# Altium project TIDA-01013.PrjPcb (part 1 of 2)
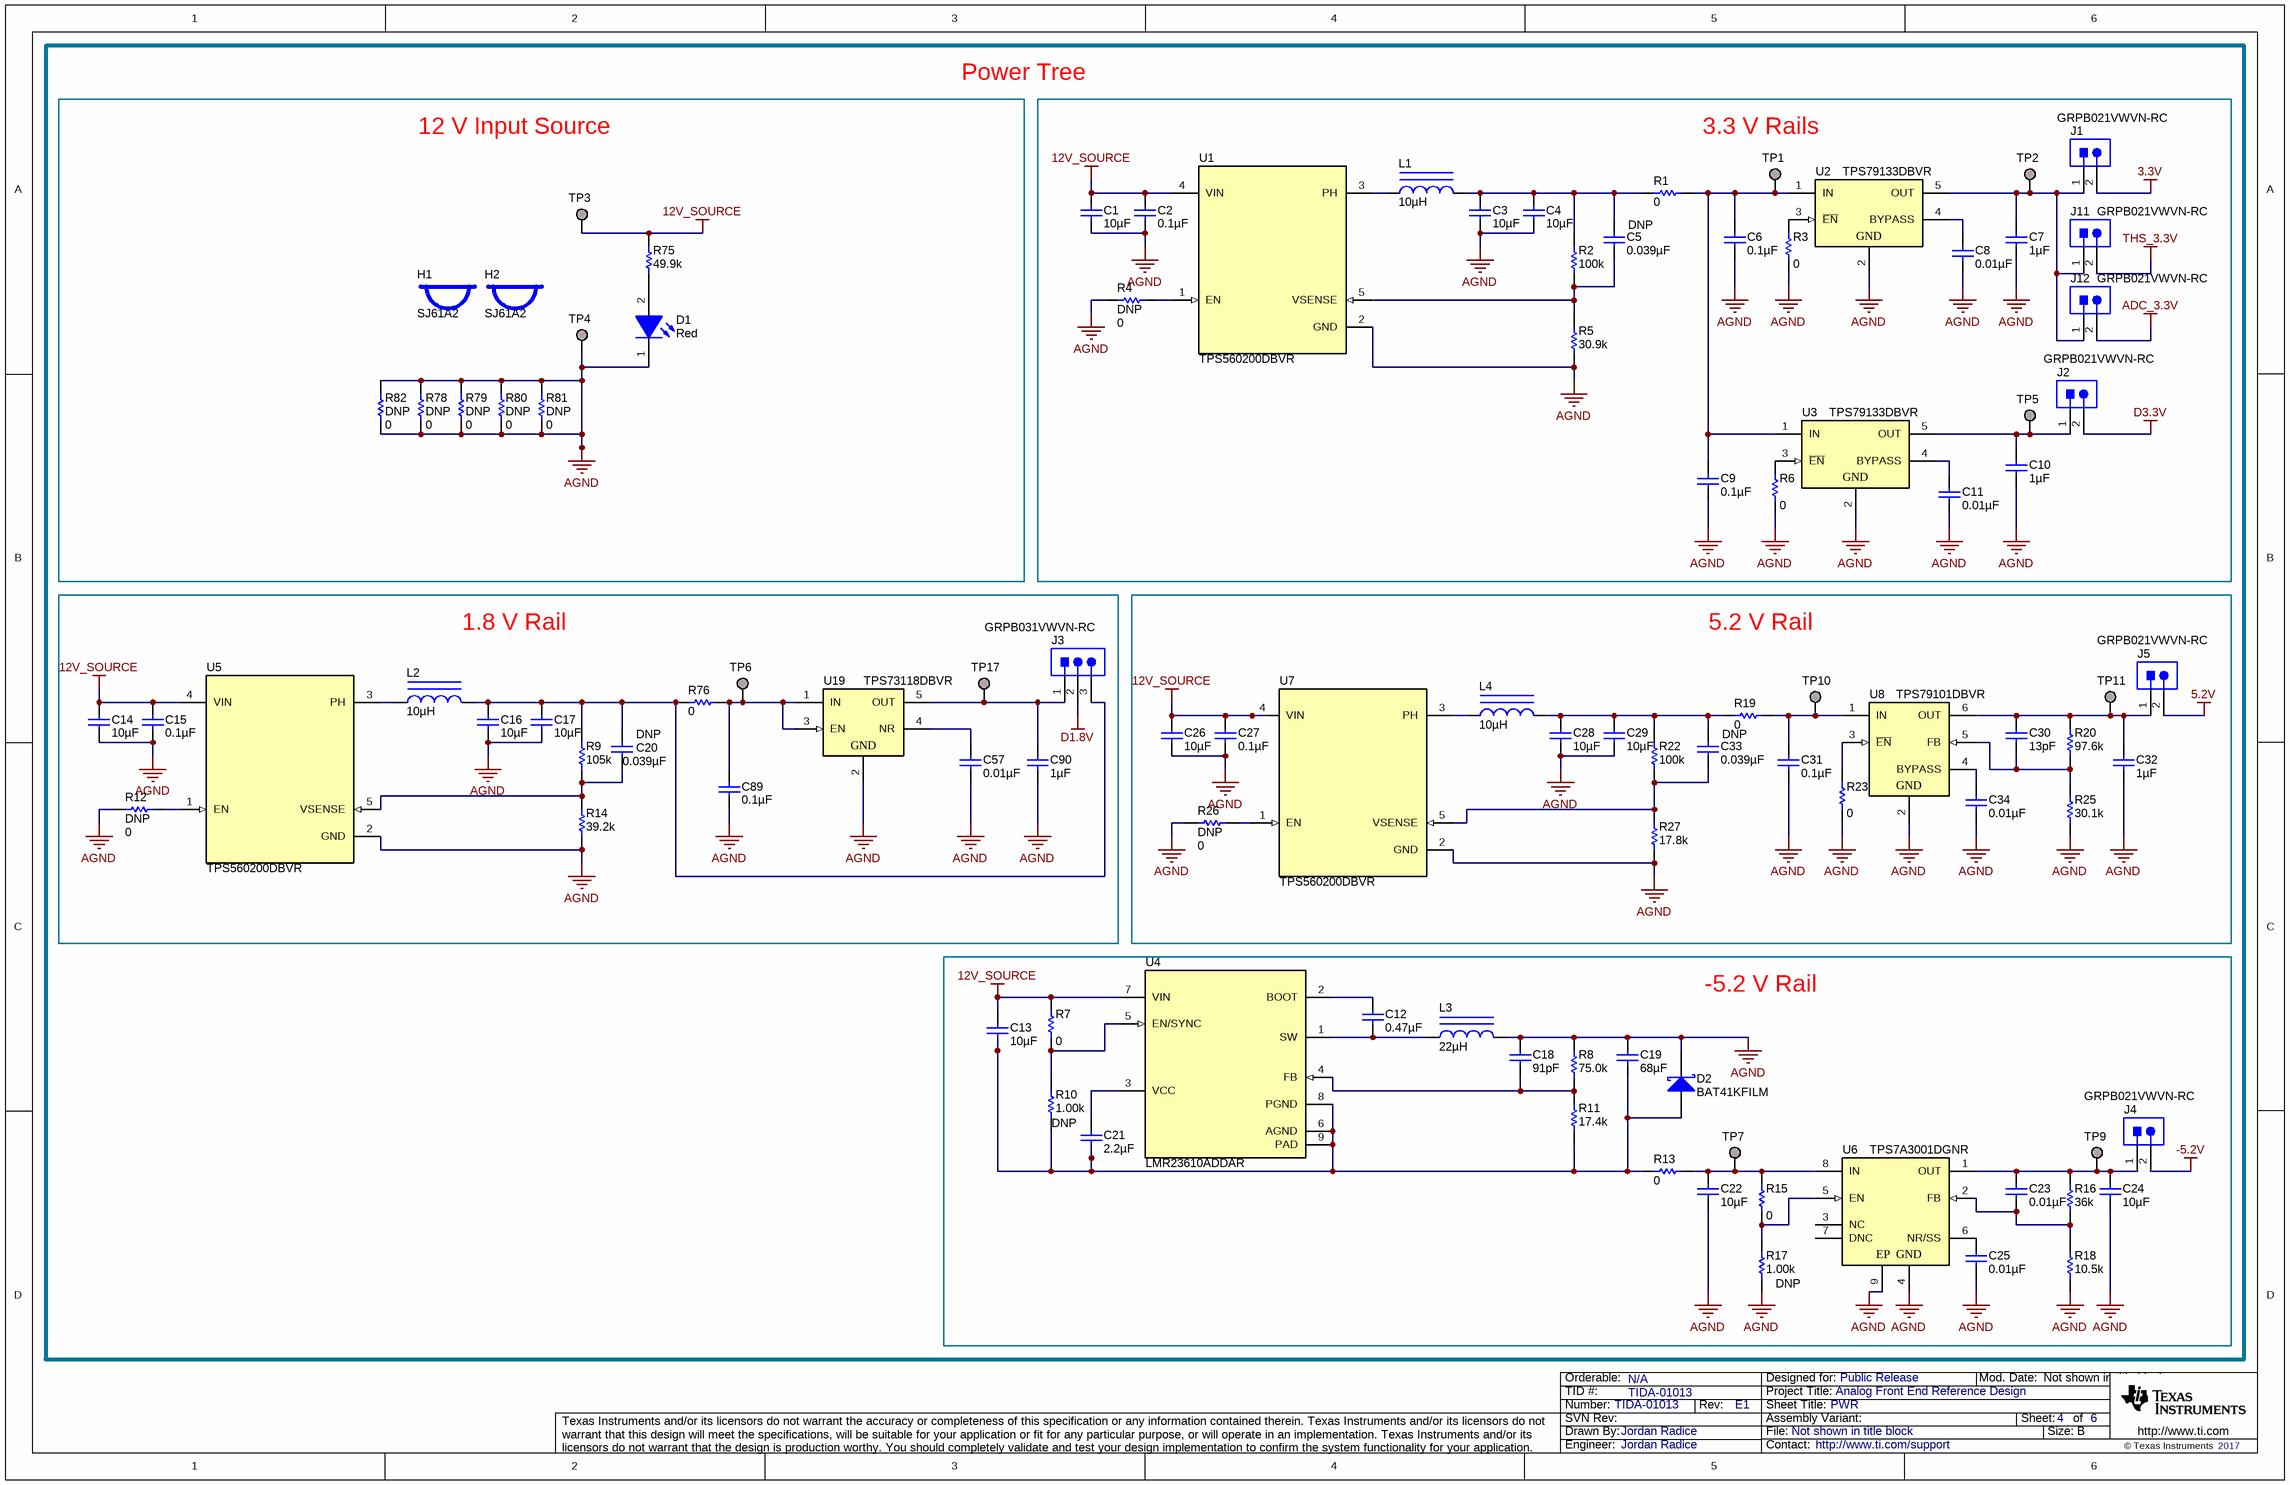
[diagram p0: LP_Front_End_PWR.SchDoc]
CopyrightYear: 2017; EVM_Orderable: N/A; PCB_Layout: Dee Lim; PCB_Rev: E1; PRJ_Customer: Public Release; PRJ_Engineer: Jordan Radice; PRJ_Number: TIDA-01013; PRJ_Title: Analog Front End Reference Design; SCH_Rev: E1; TechSupport: http://www.ti.com/support; TID: TIDA-01013
6 sheets, 219 parts. Net scope: global (net labels, ports and power ports of the same name join across sheets).
Board file: TIDA-01013.PcbDoc
Sheets:
  LP_Front_End_PWR.SchDoc
  LP_Front_End_ClockTree.SchDoc
  LP_Front_End_AFE.SchDoc
  LP_Front_End_ADC.SchDoc
  LP_Front_End_Block_Diagram.SchDoc
  TIDA-01013_EVM_Hardware.SchDoc

## Sheet LP_Front_End_PWR.SchDoc: PWR
size 431 x 279 mm; Date: Not shown in title block; ApprovedBy: Not shown in title block; CheckedBy: Not shown in title block; Author: Not shown in title block; CompanyName: Not shown in title block; DrawnBy: Jordan Radice; Engineer: Not shown in title block; Organization: Not shown in title block; Address1: Not shown in title block; Address2: Not shown in title block; Address3: Not shown in title block; Address4: Not shown in title block; DocumentNumber: 1; Revision: Use project parameter SCH_Rev; SheetNumber: 4; SheetTotal: 6; PageSetup: Record=PageOptions¦CenterHorizontal=True¦CenterVertical=True¦PrintScale=0.96¦XCorrection=1.00¦YCorrection=1.00¦PrintKind=0¦BorderSize=5000000¦LeftOffset=0¦BottomOffset=0¦Orientation=2¦PaperLength=1000¦PaperWidth=1000¦Scale=100¦PaperSource=15¦PrintQuality=-3¦MediaType=1¦DitherType=10¦PrintScaleMode=1¦PaperKind=11x17¦PaperIndex=17

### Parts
C1  ValueDisplayed: 10µF  [0603]  (hidden comment: C1608X5R1E106M080AC)
C2  ValueDisplayed: 0.1µF  [0402]  (hidden comment: GRM155R61E104KA87D)
C3  ValueDisplayed: 10µF  [0603]  (hidden comment: C1608X5R1E106M080AC)
C4  ValueDisplayed: 10µF  [0603]  (hidden comment: C1608X5R1E106M080AC)
C5  DNP  ValueDisplayed: 0.039µF  [0402]
C6  ValueDisplayed: 0.1µF  [0402]  (hidden comment: GRM155R61E104KA87D)
C7  ValueDisplayed: 1µF  [0402]  (hidden comment: GRM155R61E105KA12D)
C8  ValueDisplayed: 0.01µF  [0603]  (hidden comment: GRM188R61H103KA01D)
C9  ValueDisplayed: 0.1µF  [0402]  (hidden comment: GRM155R61E104KA87D)
C10  ValueDisplayed: 1µF  [0402]  (hidden comment: GRM155R61E105KA12D)
C11  ValueDisplayed: 0.01µF  [0603]  (hidden comment: GRM188R61H103KA01D)
C12  ValueDisplayed: 0.47µF  [0603]  (hidden comment: GRM188R61E474KA12D)
C13  ValueDisplayed: 10µF  [0603]  (hidden comment: C1608X5R1E106M080AC)
C14  ValueDisplayed: 10µF  [0603]  (hidden comment: C1608X5R1E106M080AC)
C15  ValueDisplayed: 0.1µF  [0402]  (hidden comment: GRM155R61E104KA87D)
C16  ValueDisplayed: 10µF  [0603]  (hidden comment: C1608X5R1E106M080AC)
C17  ValueDisplayed: 10µF  [0603]  (hidden comment: C1608X5R1E106M080AC)
C18  ValueDisplayed: 91pF  [0402]  (hidden comment: GRM1555C1H910JA01D)
C19  ValueDisplayed: 68µF  [1206_190]  (hidden comment: C3216X5R1A686M160AC)
C20  DNP  ValueDisplayed: 0.039µF  [0402]
C21  ValueDisplayed: 2.2µF  [0402]  (hidden comment: C1005X5R1E225K050BC)
C22  ValueDisplayed: 10µF  [0603]  (hidden comment: C1608X5R1E106M080AC)
C23  ValueDisplayed: 0.01µF  [0603]  (hidden comment: GRM188R61H103KA01D)
C24  ValueDisplayed: 10µF  [0603]  (hidden comment: C1608X5R1E106M080AC)
C25  ValueDisplayed: 0.01µF  [0603]  (hidden comment: GRM188R61H103KA01D)
C26  ValueDisplayed: 10µF  [0603]  (hidden comment: C1608X5R1E106M080AC)
C27  ValueDisplayed: 0.1µF  [0402]  (hidden comment: GRM155R61E104KA87D)
C28  ValueDisplayed: 10µF  [0603]  (hidden comment: C1608X5R1E106M080AC)
C29  ValueDisplayed: 10µF  [0603]  (hidden comment: C1608X5R1E106M080AC)
C30  ValueDisplayed: 13pF  [0402]  (hidden comment: GRM1555C1H130JA01D)
C31  ValueDisplayed: 0.1µF  [0402]  (hidden comment: GRM155R61E104KA87D)
C32  ValueDisplayed: 1µF  [0402]  (hidden comment: GRM155R61E105KA12D)
C33  DNP  ValueDisplayed: 0.039µF  [0402]
C34  ValueDisplayed: 0.01µF  [0603]  (hidden comment: GRM188R61H103KA01D)
C57  ValueDisplayed: 0.01µF  [0603]  (hidden comment: GRM188R61H103KA01D)
C89  ValueDisplayed: 0.1µF  [0402]  (hidden comment: GRM155R61E104KA87D)
C90  ValueDisplayed: 1µF  [0402]  (hidden comment: GRM155R61E105KA12D)
D1  value Red  [WL-SMCW_RED]  (hidden comment: 150060RS75000)
D2  BAT41KFILM  [SOD-523]
H1  SJ61A2  [Bumpon_SJ61A2]
H2  SJ61A2  [Bumpon_SJ61A2]
J1  GRPB021VWVN-RC  [Sullins_GRPB021VWVN-RC]
J2  GRPB021VWVN-RC  [Sullins_GRPB021VWVN-RC]
J3  GRPB031VWVN-RC  [Sullins_GRPB031VWVN-RC]
J4  GRPB021VWVN-RC  [Sullins_GRPB021VWVN-RC]
J5  GRPB021VWVN-RC  [Sullins_GRPB021VWVN-RC]
J11  GRPB021VWVN-RC  [Sullins_GRPB021VWVN-RC]
J12  GRPB021VWVN-RC  [Sullins_GRPB021VWVN-RC]
L1  ValueDisplayed: 10µH  [SRN2010TA]  (hidden comment: SRN2010TA-100M)
L2  ValueDisplayed: 10µH  [SRN2010TA]  (hidden comment: SRN2010TA-100M)
L3  ValueDisplayed: 22µH  [SRU2016]  (hidden comment: SRU2016-220Y)
L4  ValueDisplayed: 10µH  [SRN2010TA]  (hidden comment: SRN2010TA-100M)
R1  ValueDisplayed: 0  [0603]  (hidden comment: CRCW06030000Z0EA)
R2  ValueDisplayed: 100k  [0402]  (hidden comment: CRCW0402100KFKED)
R3  ValueDisplayed: 0  [0402]
R4  DNP  ValueDisplayed: 0  [0402]
R5  ValueDisplayed: 30.9k  [0402]  (hidden comment: CRCW040230K9FKED)
R6  ValueDisplayed: 0  [0402]
R7  ValueDisplayed: 0  [0402]
R8  ValueDisplayed: 75.0k  [0402]  (hidden comment: CRCW040275K0FKED)
R9  ValueDisplayed: 105k  [0402]  (hidden comment: CRCW0402105KFKED)
R10  DNP  ValueDisplayed: 1.00k  [0402]
R11  ValueDisplayed: 17.4k  [0402]  (hidden comment: CRCW040217K4FKED)
R12  DNP  ValueDisplayed: 0  [0402]
R13  ValueDisplayed: 0  [0603]  (hidden comment: CRCW06030000Z0EA)
R14  ValueDisplayed: 39.2k  [0402]  (hidden comment: CRCW040239K2FKED)
R15  ValueDisplayed: 0  [0402]
R16  ValueDisplayed: 36k  [0402]  (hidden comment: CRCW040236K0JNED)
R17  DNP  ValueDisplayed: 1.00k  [0402]
R18  ValueDisplayed: 10.5k  [0402]  (hidden comment: CRCW040210K5FKED)
R19  ValueDisplayed: 0  [0603]  (hidden comment: CRCW06030000Z0EA)
R20  ValueDisplayed: 97.6k  [0402]  (hidden comment: ERJ-2RKF9762X)
R22  ValueDisplayed: 100k  [0402]  (hidden comment: RC0402FR-07100KL)
R23  ValueDisplayed: 0  [0402]
R25  ValueDisplayed: 30.1k  [0402]  (hidden comment: RC0402FR-0730K1L)
R26  DNP  ValueDisplayed: 0  [0402]
R27  ValueDisplayed: 17.8k  [0402]  (hidden comment: CRCW040217K8FKED)
R75  ValueDisplayed: 49.9k  [0402]  (hidden comment: PCF0402-03-49K9BT1)
R76  ValueDisplayed: 0  [0603]  (hidden comment: CRCW06030000Z0EA)
R78  DNP  ValueDisplayed: 0  [0603]
R79  DNP  ValueDisplayed: 0  [0603]
R80  DNP  ValueDisplayed: 0  [0603]
R81  DNP  ValueDisplayed: 0  [0603]
R82  DNP  ValueDisplayed: 0  [0603]
TP1  TESTPOINT  [TP_SM_1MM]  (value not drawn)  (no BOM)
TP2  TESTPOINT  [TP_SM_1MM]  (value not drawn)  (no BOM)
TP3  TESTPOINT  [Keystone_5019]  (value not drawn)  (no BOM)
TP4  TESTPOINT  [Keystone_5019]  (value not drawn)  (no BOM)
TP5  TESTPOINT  [TP_SM_1MM]  (value not drawn)  (no BOM)
TP6  TESTPOINT  [TP_SM_1MM]  (value not drawn)  (no BOM)
TP7  TESTPOINT  [TP_SM_1MM]  (value not drawn)  (no BOM)
TP9  TESTPOINT  [TP_SM_1MM]  (value not drawn)  (no BOM)
TP10  TESTPOINT  [TP_SM_1MM]  (value not drawn)  (no BOM)
TP11  TESTPOINT  [TP_SM_1MM]  (value not drawn)  (no BOM)
TP17  TESTPOINT  [TP_SM_1MM]  (value not drawn)  (no BOM)
U1  TPS560200DBVR  [DBV0005A_N]
U2  TPS79133DBVR  [DBV0005A_N]
U3  TPS79133DBVR  [DBV0005A_N]
U4  LMR23610ADDAR  [DDA0008E_N]
U5  TPS560200DBVR  [DBV0005A_N]
U6  TPS7A3001DGNR  [DGN0008D_N]
U7  TPS560200DBVR  [DBV0005A_N]
U8  TPS79101DBVR  [DBV0006A_N]
U19  TPS73118DBVR  [DBV0005A_N]

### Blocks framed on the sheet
12 V Input Source: D1 H1 H2 R75 R78-R82 TP3 TP4
3.3 V Rails: C1-C11 J1 J2 J11 J12 L1 R1-R6 TP1 TP2 TP5 U1-U3
1.8 V Rail: C14-C17 C20 C57 C89 C90 J3 L2 R9 R12 R14 R76 TP6 TP17 U5 U19
5.2 V Rail: C26-C34 J5 L4 R19 R20 R22 R23 R25-R27 TP10 TP11 U7 U8
-5.2 V Rail: C12 C13 C18 C19 C21-C25 D2 J4 L3 R7 R8 R10 R11 R13 R15-R18 TP7 TP9 U4 U6

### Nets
3.3V: J1.2
5.2V: J5.2
12V_SOURCE: C1.1 C2.1 C13.1 C14.1 C15.1 C26.1 C27.1 R7.1 R75.2 TP3.1 U1.4(VIN) U4.7(VIN) U5.4(VIN) U7.4(VIN)
-5.2V: J4.2
ADC_3.3V: J12.2
AGND: C1.2 C2.2 C3.2 C4.2 C6.2 C7.2 C8.2 C9.2 C10.2 C11.2 C14.2 C15.2 C16.2 C17.2 C18.1 C19.1 C22.2 C24.2 C25.2 C26.2 C27.2 C28.2 C29.2 C31.2 C32.2 C34.2 C57.2 C89.2 C90.2 D1.1(K) D2.1(K) L3.2 R3.2 R4.2 R5.1 R6.2 R8.2 R12.2 R14.1 R17.1 R18.1 R23.2 R25.1 R26.2 R27.1 R78.1 R78.2 R79.1 R79.2 R80.1 R80.2 R81.1 R81.2 R82.1 R82.2 TP4.1 U1.2(GND) U2.2(GND) U3.2(GND) U5.2(GND) U6.4(GND) U6.9(EP) U7.2(GND) U8.2(GND) U19.2(GND)
D1.8V: J3.2
D3.3V: J2.2
THS_3.3V: J11.2
NetC3_1: C3.1 C4.1 C5.1 L1.2 R1.1 R2.2
NetC5_2: C5.2 R2.1 R5.2 U1.5(VSENSE)
NetC6_1: C6.1 C9.1 R1.2 TP1.1 U2.1(IN) U3.1(IN)
NetC7_1: C7.1 J1.1 J11.1 J12.1 TP2.1 U2.5(OUT)
NetC8_1: C8.1 U2.4(BYPASS)
NetC10_1: C10.1 J2.1 TP5.1 U3.5(OUT)
NetC11_1: C11.1 U3.4(BYPASS)
NetC12_1: C12.1 U4.2(BOOT)
NetC12_2: C12.2 L3.1 U4.1(SW)
NetC13_2: C13.2 C19.2 C21.2 D2.2(A) R10.1 R11.1 R13.1 U4.6(AGND) U4.8(PGND) U4.9(PAD)
NetC16_1: C16.1 C17.1 C20.1 J3.3 L2.2 R9.2 R76.1
NetC18_2: C18.2 R8.1 R11.2 U4.4(FB)
NetC20_2: C20.2 R9.1 R14.2 U5.5(VSENSE)
NetC21_1: C21.1 U4.3(VCC)
NetC22_1: C22.1 R13.2 R15.1 TP7.1 U6.8(IN)
NetC23_1: C23.1 C24.1 J4.1 R16.2 TP9.1 U6.1(OUT)
NetC23_2: C23.2 R16.1 R18.2 U6.2(FB)
NetC25_1: C25.1 U6.6(NR/SS)
NetC28_1: C28.1 C29.1 C33.1 L4.2 R19.1 R22.2
NetC30_1: C30.1 C32.1 J5.1 R20.2 TP11.1 U8.6(OUT)
NetC30_2: C30.2 R20.1 R25.2 U8.5(FB)
NetC31_1: C31.1 R19.2 TP10.1 U8.1(IN)
NetC33_2: C33.2 R22.1 R27.2 U7.5(VSENSE)
NetC34_1: C34.1 U8.4(BYPASS)
NetC57_1: C57.1 U19.4(NR)
NetC89_1: C89.1 R76.2 TP6.1 U19.1(IN) U19.3(EN)
NetC90_1: C90.1 J3.1 TP17.1 U19.5(OUT)
NetD1_2: D1.2(A) R75.1
NetL1_1: L1.1 U1.3(PH)
NetL2_1: L2.1 U5.3(PH)
NetL4_1: L4.1 U7.3(PH)
NetR3_1: R3.1 U2.3(~{EN})
NetR4_1: R4.1 U1.1(EN)
NetR6_1: R6.1 U3.3(~{EN})
NetR7_2: R7.2 R10.2 U4.5(EN/SYNC)
NetR12_1: R12.1 U5.1(EN)
NetR15_2: R15.2 R17.2 U6.5(EN)
NetR23_1: R23.1 U8.3(~{EN})
NetR26_1: R26.1 U7.1(EN)

Not connected (* = marked no-connect by the designer): U6 3(NC) 7(DNC)

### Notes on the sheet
- Power Tree

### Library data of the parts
C1 C3 C4 C13 C14 C16 C17 C22 C24 C26 C28 C29 = C1608X5R1E106M080AC: CAP, CERM, 10 µF, 25 V, +/- 20%, X5R, 0603; Manufacturer: TDK; Polarized: N; CompType: Capacitor; Value: 10uF; U/M: EA; Cap_F: 0.00001; Tolerance_%: 20; ESR_ohm: 0.004639; Value1: 0.004639 ohm; VDC_V: 25; Value2: 25V; IRMS_A: 2.41407; TaMin_C: -55; TaMax_C: 85; SizeArea_mm2: 1.28; SizeAreaWB_mm2: 4.68; SizeX_mm: 1.6; SizeY_mm: 0.8; SizeZ_mm: 1; AEC Category: Q200
C2 C6 C9 C15 C27 C31 C89 = GRM155R61E104KA87D: CAP, CERM, 0.1 µF, 25 V, +/- 10%, X5R, 0402; Manufacturer: MuRata; Polarized: N; CompType: Capacitor; Value: 0.1uF; U/M: EA; Cap_F: 0.0000001; Tolerance_%: 10; Value1: Unknown; VDC_V: 25; Value2: 25V; TaMin_C: -55; TaMax_C: 85; SizeArea_mm2: 0.5; SizeAreaWB_mm2: 3; SizeX_mm: 1; SizeZ_mm: 0.6; AEC Category: Q200
C5 C20 C33 = GRM155R71A393KA01D: CAP, CERM, 0.039 µF, 10 V, +/- 10%, X7R, 0402; Manufacturer: MuRata; Polarized: N; CompType: Capacitor; Value: 0.039uF; U/M: EA; Cap_F: 0.000000039; Tolerance_%: 10; Value1: Unknown; Value2: 10V; TaMin_C: -55; TaMax_C: 125; SizeArea_mm2: 0.5; SizeAreaWB_mm2: 3; SizeX_mm: 1; SizeZ_mm: 0.6; AEC Category: Q200
C7 C10 C32 C90 = GRM155R61E105KA12D: CAP, CERM, 1 µF, 25 V, +/- 10%, X5R, 0402; Manufacturer: MuRata; Polarized: N; CompType: Capacitor; Value: 1uF; U/M: EA; Cap_F: 0.000001; Tolerance_%: 10; Value1: Unknown; VDC_V: 25; Value2: 25V; TaMin_C: -55; TaMax_C: 85; SizeArea_mm2: 0.5; SizeAreaWB_mm2: 3; SizeX_mm: 1; SizeZ_mm: 0.6; AEC Category: Q200
C8 C11 C23 C25 C34 C57 = GRM188R61H103KA01D: CAP, CERM, 0.01 µF, 50 V, +/- 10%, X5R, 0603; Manufacturer: MuRata; Polarized: N; CompType: Capacitor; Value: 0.01uF; U/M: EA; Cap_F: 0.00000001; Tolerance_%: 10; Value1: Unknown; VDC_V: 50; Value2: 50V; TaMin_C: -55; TaMax_C: 85; SizeArea_mm2: 1.28; SizeAreaWB_mm2: 4.68; SizeX_mm: 1.6; SizeY_mm: 0.8; SizeZ_mm: 1; AEC Category: Q200
C12 = GRM188R61E474KA12D: CAP, CERM, 0.47 µF, 25 V, +/- 10%, X5R, 0603; Manufacturer: MuRata; Polarized: N; CompType: Capacitor; Value: 0.47uF; U/M: EA; Cap_F: 0.00000047; Tolerance_%: 10; Value1: Unknown; VDC_V: 25; Value2: 25V; TaMin_C: -55; TaMax_C: 85; SizeArea_mm2: 1.28; SizeAreaWB_mm2: 4.68; SizeX_mm: 1.6; SizeY_mm: 0.8; SizeZ_mm: 1; AEC Category: Q200
C18 = GRM1555C1H910JA01D: CAP, CERM, 91 pF, 50 V, +/- 5%, C0G/NP0, 0402; Manufacturer: MuRata; Polarized: N; CompType: Capacitor; Value: 91pF; U/M: EA; Cap_F: 0.000000000091; Tolerance_%: 5; Value1: Unknown; VDC_V: 50; Value2: 50V; TaMin_C: -55; TaMax_C: 125; SizeArea_mm2: 0.5; SizeAreaWB_mm2: 3; SizeX_mm: 1; SizeZ_mm: 0.6; AEC Category: Q200
C19 = C3216X5R1A686M160AC: CAP, CERM, 68 µF, 10 V, +/- 20%, X5R, 1206_190; Manufacturer: TDK; Polarized: N; CompType: Capacitor; Value: 68uF; U/M: EA; Cap_F: 0.000068; Tolerance_%: 20; ESR_ohm: 0.003494; Value1: 0.003494 ohm; VDC_V: 10; Value2: 10V; IRMS_A: 3.8813; TaMin_C: -55; TaMax_C: 85; SizeArea_mm2: 5.12; SizeAreaWB_mm2: 10.92; SizeX_mm: 3.2; SizeY_mm: 1.6; SizeZ_mm: 1.9; AEC Category: Q200
C21 = C1005X5R1E225K050BC: CAP, CERM, 2.2 µF, 25 V, +/- 10%, X5R, 0402; Manufacturer: TDK; Polarized: N; CompType: Capacitor; Value: 2.2uF; U/M: EA; Cap_F: 0.0000022; Tolerance_%: 10; Value1: Unknown; VDC_V: 25; Value2: 25V; TaMin_C: -55; TaMax_C: 85; SizeArea_mm2: 0.5; SizeAreaWB_mm2: 3; SizeX_mm: 1; SizeZ_mm: 0.6; AEC Category: Q200
C30 = GRM1555C1H130JA01D: CAP, CERM, 13 pF, 50 V, +/- 5%, C0G/NP0, 0402; Manufacturer: MuRata; Polarized: N; CompType: Capacitor; Value: 13pF; U/M: EA; Cap_F: 0.000000000013; Tolerance_%: 5; Value1: Unknown; VDC_V: 50; Value2: 50V; TaMin_C: -55; TaMax_C: 125; SizeArea_mm2: 0.5; SizeAreaWB_mm2: 3; SizeX_mm: 1; SizeZ_mm: 0.6; AEC Category: Q200
D1 = 150060RS75000: LED, Red, SMD; Manufacturer: Wurth Elektronik; Type: AlInGaP; Vf_V: 2; Value2: 2V; Io_A: 0.03; Vr_V: 5; Tjmax_C: 85; Power_TotalModule: 0.072; Value1: 0.072W; Angle: 140; U/M: EA
D2 = BAT41KFILM: Diode, Schottky, 100 V, 0.2 A, SOD-523; Manufacturer: STMicroelectronics; U/M: EA; Vf_V: 1; Value: 100V; Value1: 0.2A; Value2: 1V; Io_A: 0.2; Vr_V: 100; TJmax_C: 150; SizeAreaWB_mm2: 5.13; SizeArea_mm2: 1.53; SizeX_mm: 1.7; SizeY_mm: 0.9; SizeZ_mm: 0.65; AEC Category: Q101; AEC Qualified: N
H1 H2 = SJ61A2: Bumpon, Hemisphere, 0.375 X 0.235, Black; Manufacturer: 3M; SymbolCreator: a0412235
J1 J2 J4 J5 J11 J12 = GRPB021VWVN-RC: Header, 50mil, 2x1, Gold, TH; Manufacturer: Sullins Connector Solutions; SymbolCreator: a0412235
J3 = GRPB031VWVN-RC: Header, 50mil, 3x1, Gold, TH; Manufacturer: Sullins Connector Solutions; SymbolCreator: a0799628; Gender: Male; Shrouded: N; Row_Count: 1
L1 L2 L4 = SRN2010TA-100M: Inductor, Shielded, Ferrite, 10 µH, 0.45 A, 0.864 ohm, AEC-Q200 Grade 1, SMD; Manufacturer: Bourns; Value: 10uH; Ind_H: 10.0E-6; Imax_A: 0.45; Irms: 0.45A @ 40C rise; Isat: 0.55A @ 30% inductance drop; DCR_ohm: 0.864; Value2: 0.45A; SizeAreaWB_mm2: 7.8; SizeArea_mm2: 3.2; SizeX_mm: 2; SizeY_mm: 1.6; SizeZ_mm: 1; AEC Category: Q200; AEC Qualified: Y
L3 = SRU2016-220Y: Inductor, Drum Core, Ferrite, 22 µH, 0.37 A, 0.99 ohm, SMD; Manufacturer: Bourns; Value: 22uH; Ind_H: 22.0E-6; Imax_A: 0.37; Irms: 0.43A @ 40C rise; Isat: 0.37A @ 35% inductance drop; DCR_ohm: 0.99; Value2: 0.37A; SizeAreaWB_mm2: 14.44; SizeArea_mm2: 7.84; SizeX_mm: 2.8; SizeZ_mm: 1.65; AEC Category: Q200
R1 R13 R19 R76 R78-R82 = CRCW06030000Z0EA: RES, 0, 5%, 0.1 W, 0603; Manufacturer: Vishay-Dale; CompType: Resistor; Value: 0; Value_Code: 0000; Tolerance_%: 5; Power_W: 0.1; Value2: 0.1W; VDC_V: 75; TempCo: 200 ppm/C; SizeArea_mm2: 1.28; SizeX_mm: 1.6; SizeY_mm: 0.8; SizeZ_mm: 1; EIA_Code: E24; U/M: EA; AEC Category: Q200
R2 = CRCW0402100KFKED: RES, 100 k, 1%, 0.063 W, 0402; Manufacturer: Vishay-Dale; CompType: Resistor; Value: 100k; Res_ohm: 100000; Tolerance_%: 1; Power_W: 0.063; Value2: 0.063W; VDC_V: 50; TempCo: 100 ppm/C; SizeArea_mm2: 0.5; SizeZ_mm: 0.6; EIA_Code: E96; U/M: EA; AEC Category: Q200
R3 R4 R6 R7 R12 R15 R23 R26 = CRCW04020000Z0ED: RES, 0, 5%, 0.063 W, 0402; Manufacturer: Vishay-Dale; CompType: Resistor; Value: 0; Value_Code: 0000; Tolerance_%: 5; Power_W: 0.063; Value2: 0.063W; VDC_V: 50; TempCo: 200 ppm/C; SizeArea_mm2: 0.5; SizeX_mm: 1; SizeZ_mm: 0.6; EIA_Code: E24; U/M: EA; AEC Category: Q200
R5 = CRCW040230K9FKED: RES, 30.9 k, 1%, 0.063 W, 0402; Manufacturer: Vishay-Dale; CompType: Resistor; Value: 30.9k; Res_ohm: 30900; Value_Code: 30k9; Tolerance_%: 1; Power_W: 0.063; Value2: 0.063W; VDC_V: 50; TempCo: 100 ppm/C; SizeArea_mm2: 0.5; SizeZ_mm: 0.6; EIA_Code: E96; U/M: EA; AEC Category: Q200
R8 = CRCW040275K0FKED: RES, 75.0 k, 1%, 0.063 W, 0402; Manufacturer: Vishay-Dale; CompType: Resistor; Value: 75.0k; Res_ohm: 75000; Value_Code: 75k0; Tolerance_%: 1; Power_W: 0.063; Value2: 0.063W; VDC_V: 50; TempCo: 100 ppm/C; SizeArea_mm2: 0.5; SizeZ_mm: 0.6; EIA_Code: E96; U/M: EA; AEC Category: Q200
R9 = CRCW0402105KFKED: RES, 105 k, 1%, 0.063 W, 0402; Manufacturer: Vishay-Dale; CompType: Resistor; Value: 105k; Res_ohm: 105000; Tolerance_%: 1; Power_W: 0.063; Value2: 0.063W; VDC_V: 50; TempCo: 100 ppm/C; SizeArea_mm2: 0.5; SizeZ_mm: 0.6; EIA_Code: E96; U/M: EA; AEC Category: Q200
R10 R17 = RC0402FR-071KL: RES, 1.00 k, 1%, 0.0625 W, 0402; Manufacturer: Yageo America; CompType: Resistor; Value: 1.00k; Res_ohm: 1000; Value_Code: 1k00; Tolerance_%: 1; Power_W: 0.0625; VDC_V: 50; TempCo: 100 ppm/C; SizeArea_mm2: 0.5; SizeZ_mm: 0.6; EIA_Code: E96; U/M: EA; AEC Category: Q200; AEC Qualified: N
R11 = CRCW040217K4FKED: RES, 17.4 k, 1%, 0.063 W, 0402; Manufacturer: Vishay-Dale; CompType: Resistor; Value: 17.4k; Res_ohm: 17400; Value_Code: 17k4; Tolerance_%: 1; Power_W: 0.063; Value2: 0.063W; VDC_V: 50; TempCo: 100 ppm/C; SizeArea_mm2: 0.5; SizeZ_mm: 0.6; EIA_Code: E96; U/M: EA; AEC Category: Q200
R14 = CRCW040239K2FKED: RES, 39.2 k, 1%, 0.063 W, 0402; Manufacturer: Vishay-Dale; CompType: Resistor; Value: 39.2k; Res_ohm: 39200; Value_Code: 39k2; Tolerance_%: 1; Power_W: 0.063; Value2: 0.063W; VDC_V: 50; TempCo: 100 ppm/C; SizeArea_mm2: 0.5; SizeZ_mm: 0.6; EIA_Code: E96; U/M: EA; AEC Category: Q200
R16 = CRCW040236K0JNED: RES, 36 k, 5%, 0.063 W, 0402; Manufacturer: Vishay-Dale; CompType: Resistor; Value: 36k; Res_ohm: 36000; Value_Code: 36k0; Tolerance_%: 5; Power_W: 0.063; Value2: 0.063W; VDC_V: 50; TempCo: 200 ppm/C; SizeArea_mm2: 0.5; SizeX_mm: 1; SizeZ_mm: 0.6; EIA_Code: E24; U/M: EA; AEC Category: Q200
R18 = CRCW040210K5FKED: RES, 10.5 k, 1%, 0.063 W, 0402; Manufacturer: Vishay-Dale; CompType: Resistor; Value: 10.5k; Res_ohm: 10500; Value_Code: 10k5; Tolerance_%: 1; Power_W: 0.063; Value2: 0.063W; VDC_V: 50; TempCo: 100 ppm/C; SizeArea_mm2: 0.5; SizeZ_mm: 0.6; EIA_Code: E96; U/M: EA; AEC Category: Q200
R20 = ERJ-2RKF9762X: RES, 97.6 k, 1%, 0.1 W, AEC-Q200 Grade 0, 0402; Manufacturer: Panasonic; CompType: Resistor; Value: 97.6k; Res_ohm: 97600; Value_Code: 97k6; Tolerance_%: 1; Power_W: 0.1; Value2: 0.1W; VDC_V: 50; TempCo: 100 ppm/C; SizeArea_mm2: 0.5; SizeZ_mm: 0.6; EIA_Code: E96; U/M: EA; AEC Category: Q200; AEC Qualified: Y; AEC Grade: 0
R22 = RC0402FR-07100KL: RES, 100 k, 1%, 0.0625 W, 0402; Manufacturer: Yageo America; CompType: Resistor; Value: 100k; Res_ohm: 100000; Tolerance_%: 1; Power_W: 0.0625; VDC_V: 50; TempCo: 100 ppm/C; SizeArea_mm2: 0.5; SizeZ_mm: 0.6; EIA_Code: E96; U/M: EA; AEC Category: Q200; AEC Qualified: N
R25 = RC0402FR-0730K1L: RES, 30.1 k, 1%, 0.063 W, 0402; Manufacturer: Yageo America; CompType: Resistor; Value: 30.1k; Res_ohm: 30100; Value_Code: 30k1; Tolerance_%: 1; Power_W: 0.063; Value2: 0.063W; VDC_V: 50; TempCo: 100 ppm/C; SizeArea_mm2: 0.5; SizeZ_mm: 0.6; EIA_Code: E96; U/M: EA; AEC Category: Q200; AEC Qualified: N
R27 = CRCW040217K8FKED: RES, 17.8 k, 1%, 0.063 W, 0402; Manufacturer: Vishay-Dale; CompType: Resistor; Value: 17.8k; Res_ohm: 17800; Value_Code: 17k8; Tolerance_%: 1; Power_W: 0.063; Value2: 0.063W; VDC_V: 50; TempCo: 100 ppm/C; SizeArea_mm2: 0.5; SizeZ_mm: 0.6; EIA_Code: E96; U/M: EA; AEC Category: Q200
R75 = PCF0402-03-49K9BT1: RES, 49.9 k, 0.1%, 0.063 W, 0402; Manufacturer: TT Electronics/IRC; CompType: Resistor; Value: 49.9k; Res_ohm: 49900; Value_Code: 49k9; Tolerance_%: 0.1; Power_W: 0.063; Value2: 0.063W; VDC_V: 25; TempCo: 25 ppm/C; SizeArea_mm2: 0.5; SizeX_mm: 1; SizeZ_mm: 0.6; EIA_Code: E192; U/M: EA; AEC Category: Q200; AEC Qualified: N
TP1 TP2 TP5-TP7 TP9-TP11 TP17 = TP_SM_1MM: 1mm Test Point, SMT; Manufacturer: Any
TP3 TP4 = 5019: Test Point, Miniature, SMT; Manufacturer: Keystone; CompType: Test Point Loop
U1 U5 U7 = TPS560200DBVR: 17V Input, 500mA Synchronous Step-Down Regulator in SOT-23 with Advanced Eco-Mode(TM), DBV0005A (SOT-5); Alternate PartNumber: TPS560200DBVT; Manufacturer: Texas Instruments; SymbolCreator: a0411947; SizeArea_mm2: 8.12; SizeAreaWB_mm2: 14.82; SizeX_mm: 2.8; SizeY_mm: 2.9; SizeZ_mm: 1.45; CompType: IC; U/M: EA
U2 U3 = TPS79133DBVR: Single Output High PSRR LDO, 100 mA, Fixed 3.3 V Output, 2.7 to 5.5 V Input, 5-pin SOT-23 (DBV), -40 to 125 degC, Green (RoHS & no Sb/Br); Manufacturer: Texas Instruments; Alternate PartNumber: Equivalent; Accuracy(%): 2; Fixed Output Options(V): 3.3; Iout(Max)(A): 0.1; Iq(Typ)(mA): 0.2; Rating: Catalog; SubFamily: Single Channel LDO; Vdo(Typ)(mV): 50; Vin(Max)(V): 5.5; Vin(Min)(V): 2.7
U4 = LMR23610ADDAR: SIMPLE SWITCHER, 36V 1A Synchronous Step-Down Converter, DDA0008E (SOIC-8); Manufacturer: Texas Instruments; SymbolCreator: a0411947; SizeArea_mm2: 31; SizeAreaWB_mm2: 57.4; SizeX_mm: 5; SizeY_mm: 6.2; SizeZ_mm: 1.7; CompType: IC; U/M: EA
U6 = TPS7A3001DGNR: Single Output High PSRR LDO, 200 mA, Adjustable -1.18 to -33 V Output, -3 to -36 V Input, with Ultra-Low Noise, 8-pin MSOP (DGN), -40 to 125 degC, Green (RoHS & no Sb/Br); Manufacturer: Texas Instruments; Alternate PartNumber: Equivalent; Accuracy(%): 1.5; Iout(Max)(A): 0.2; Iq(Typ)(mA): 0.05; SubFamily: Single Channel LDO; Vdo(Typ)(mV): 216
U8 = TPS79101DBVR: Single Output High PSRR LDO, 100 mA, Adjustable 1.2 to 5.5 V Output, 2.7 to 5.5 V Input, 6-pin SOT-23 (DBV), -40 to 125 degC, Green (RoHS & no Sb/Br); Manufacturer: Texas Instruments; Alternate PartNumber: Equivalent; Accuracy(%): 2; Iout(Max)(A): 0.1; Iq(Typ)(mA): 0.2; SubFamily: Single Channel LDO; Vdo(Typ)(mV): 38; Vin(Max)(V): 5.5; Vin(Min)(V): 2.7; Vout Adj(Min)(V): 1.2
U19 = TPS73118DBVR: Single Output Fast Transient Response LDO, 150 mA, Fixed 1.8 V Output, 1.7 to 5.5 V Input, 5-pin SOT-23 (DBV), -40 to 85 degC, Green (RoHS & no Sb/Br); Manufacturer: Texas Instruments; Alternate PartNumber: Equivalent; Accuracy(%): 1; Fixed Output Options(V): 1.8; Iout(Max)(A): 0.15; Iq(Typ)(mA): 0.4; SubFamily: Single Channel LDO; Vdo(Typ)(mV): 30; Vin(Max)(V): 5.5; Vin(Min)(V): 1.7

## Sheet LP_Front_End_ClockTree.SchDoc
size 431 x 279 mm; Date: Not shown in title block; ApprovedBy: Not shown in title block; CheckedBy: Not shown in title block; Author: Not shown in title block; CompanyName: Not shown in title block; Engineer: Not shown in title block; Organization: Not shown in title block; Address1: Not shown in title block; Address2: Not shown in title block; Address3: Not shown in title block; Address4: Not shown in title block; DocumentNumber: 1; Revision: Use project parameter SCH_Rev; SheetNumber: 5; SheetTotal: 6; PageSetup: Record=PageOptions¦CenterHorizontal=True¦CenterVertical=True¦PrintScale=0.96¦XCorrection=1.00¦YCorrection=1.00¦PrintKind=0¦BorderSize=5000000¦LeftOffset=0¦BottomOffset=0¦Orientation=2¦PaperLength=1000¦PaperWidth=1000¦Scale=100¦PaperSource=15¦PrintQuality=-3¦MediaType=1¦DitherType=10¦PrintScaleMode=1¦PaperKind=11x17¦PaperIndex=17
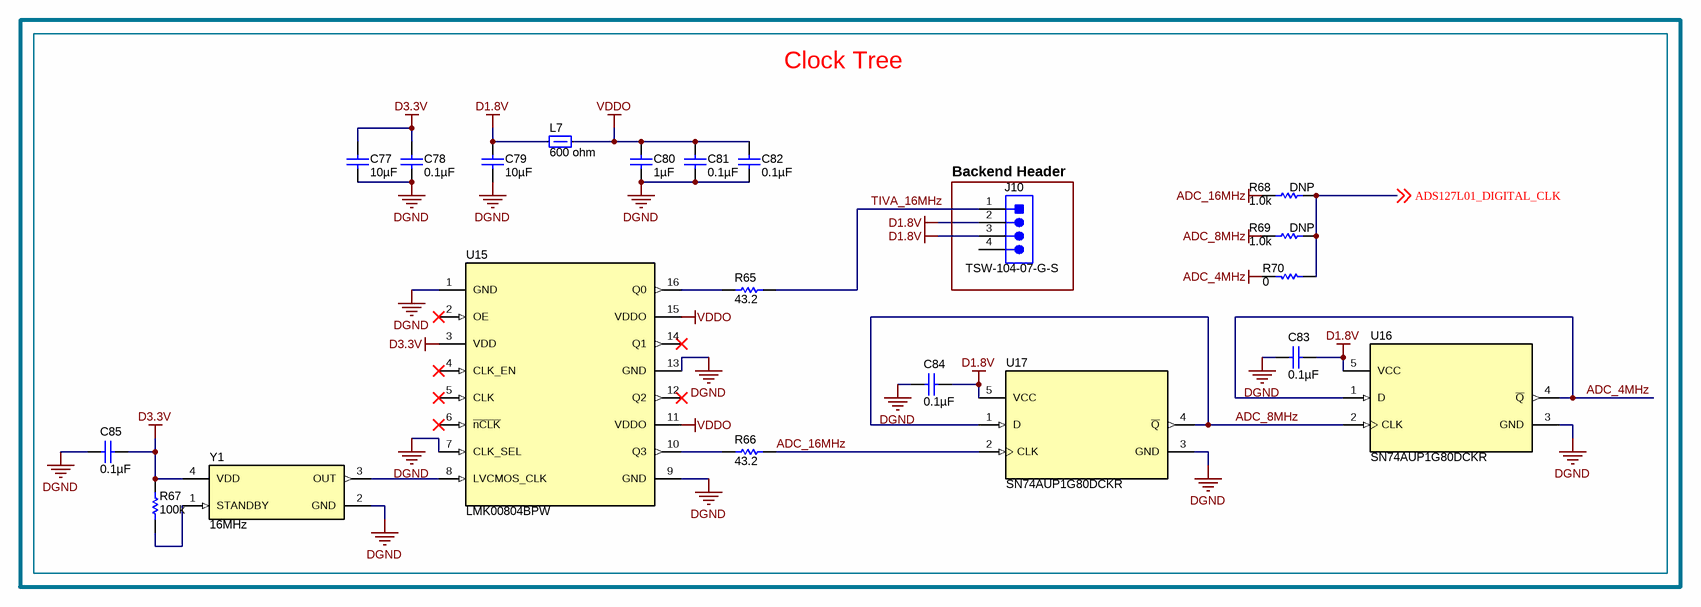
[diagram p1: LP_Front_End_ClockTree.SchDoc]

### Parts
C77  ValueDisplayed: 10µF  [0402]  (hidden comment: CL05A106MP5NUNC)
C78  ValueDisplayed: 0.1µF  [0402]  (hidden comment: C1005X5R1A104K050BA)
C79  ValueDisplayed: 10µF  [0402]  (hidden comment: CL05A106MP5NUNC)
C80  ValueDisplayed: 1µF  [0402]  (hidden comment: GRM155R61A105KE15D)
C81  ValueDisplayed: 0.1µF  [0402]  (hidden comment: C1005X5R1A104K050BA)
C82  ValueDisplayed: 0.1µF  [0402]  (hidden comment: C1005X5R1A104K050BA)
C83  ValueDisplayed: 0.1µF  [0402]  (hidden comment: C1005X5R1A104K050BA)
C84  ValueDisplayed: 0.1µF  [0402]  (hidden comment: C1005X5R1A104K050BA)
C85  ValueDisplayed: 0.1µF  [0402]  (hidden comment: C1005X5R1A104K050BA)
J10  TSW-104-07-G-S  [TSW-104-07-G-S]
L7  value 600 ohm  [0603]  (hidden comment: HZ0603C601R-10)
R65  ValueDisplayed: 43.2  [0402]  (hidden comment: CRCW040243R2FKED)
R66  ValueDisplayed: 43.2  [0402]  (hidden comment: CRCW040243R2FKED)
R67  ValueDisplayed: 100k  [0402]  (hidden comment: RMCF0402FT100K)
R68  DNP  ValueDisplayed: 1.0k  [0402]
R69  DNP  ValueDisplayed: 1.0k  [0402]
R70  ValueDisplayed: 0  [0402]
U15  LMK00804BPW  [PW0016A_N]
U16  SN74AUP1G80DCKR  [DCK0005A_N]
U17  SN74AUP1G80DCKR  [DCK0005A_N]
Y1  Frequency: 16MHz  [ABRACON_ASEMB]  (hidden comment: ASEMB-16.000MHZ-XY-T)

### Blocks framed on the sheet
Clock Tree: C77-C85 J10 L7 R65-R70 U15-U17 Y1

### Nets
ADC_4MHz: R70.2 U16.1(D) U16.4(~{Q})
ADC_8MHz: R69.2 U16.2(CLK) U17.1(D) U17.4(~{Q})
ADC_16MHz: R66.2 R68.2 U17.2(CLK)
D1.8V: C79.1 C83.1 C84.1 J10.2 J10.3 L7.1 U16.5(VCC) U17.5(VCC)
D3.3V: C77.1 C78.2 C85.2 R67.2 U15.3(VDD) Y1.4(VDD)
DGND: C77.2 C78.1 C79.2 C80.2 C81.1 C82.1 C83.2 C84.2 C85.1 U15.1(GND) U15.7(CLK_SEL) U15.9(GND) U15.13(GND) U16.3(GND) U17.3(GND) Y1.2(GND)
VDDO: C80.1 C81.2 C82.2 L7.2 U15.11(VDDO) U15.15(VDDO)
ADS127L01_DIGITAL_CLK: R68.1 R69.1 R70.1 ; off-sheet ADS127L01_DIGITAL_CLK
TIVA_16MHz: J10.1 R65.2
NetR65_1: R65.1 U15.16(Q0)
NetR66_1: R66.1 U15.10(Q3)
NetR67_1: R67.1 Y1.1(STANDBY)
NetU15_8: U15.8(LVCMOS_CLK) Y1.3(OUT)

Not connected (* = marked no-connect by the designer): J10 4; U15 2(OE)* 4(CLK_EN)* 5(CLK)* 6(~{nCLK})* 12(Q2)* 14(Q1)*

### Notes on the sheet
- (near J10) Backend Header

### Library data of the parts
C77 C79 = CL05A106MP5NUNC: CAP, CERM, 10 µF, 10 V, +/- 20%, X5R, 0402; Manufacturer: Samsung Electro-Mechanics; Polarized: N; CompType: Capacitor; Value: 10uF; U/M: EA; Cap_F: 0.00001; Tolerance_%: 20; Value1: Unknown; VDC_V: 10; Value2: 10V; TaMin_C: -55; TaMax_C: 85; SizeArea_mm2: 0.5; SizeAreaWB_mm2: 3; SizeX_mm: 1; SizeZ_mm: 0.6; AEC Category: Q200
C78 C81-C85 = C1005X5R1A104K050BA: CAP, CERM, 0.1 µF, 10 V, +/- 10%, X5R, 0402; Manufacturer: TDK; Polarized: N; CompType: Capacitor; Value: 0.1uF; U/M: EA; Cap_F: 0.0000001; Tolerance_%: 10; Value1: Unknown; Value2: 10V; TaMin_C: -55; TaMax_C: 85; SizeArea_mm2: 0.5; SizeAreaWB_mm2: 3; SizeX_mm: 1; SizeZ_mm: 0.6; AEC Category: Q200
C80 = GRM155R61A105KE15D: CAP, CERM, 1 µF, 10 V, +/- 10%, X5R, 0402; Manufacturer: MuRata; Polarized: N; CompType: Capacitor; Value: 1uF; U/M: EA; Cap_F: 0.000001; Tolerance_%: 10; Value1: Unknown; Value2: 10V; TaMin_C: -55; TaMax_C: 85; SizeArea_mm2: 0.5; SizeAreaWB_mm2: 3; SizeX_mm: 1; SizeZ_mm: 0.6; AEC Category: Q200
J10 = TSW-104-07-G-S: Header, 100mil, 4x1, Gold, TH; Manufacturer: Samtec; SymbolCreator: a0412235; Pitch_mm: 2.54; Gender: Male; Shrouded: N; Row_Count: 1; Current_A: 6.3; Voltage_V: 550; Cert_CSA: Y
L7 = HZ0603C601R-10: Ferrite Bead, 600 ohm @ 100 MHz, 0.3 A, 0603; Manufacturer: Laird-Signal Integrity Products; Imax_A: 0.3; DCR_ohm: 0.45; Value1: 0.45 ohm; Value2: 0.3A; ZTyp@100MHz_Ohm: 600
R65 R66 = CRCW040243R2FKED: RES, 43.2, 1%, 0.063 W, 0402; Manufacturer: Vishay-Dale; CompType: Resistor; Value: 43.2; Value_Code: 43R2; Tolerance_%: 1; Power_W: 0.063; Value2: 0.063W; VDC_V: 50; TempCo: 100 ppm/C; SizeArea_mm2: 0.5; SizeZ_mm: 0.6; EIA_Code: E96; U/M: EA; AEC Category: Q200
R67 = RMCF0402FT100K: RES, 100 k, 1%, 0.063 W, AEC-Q200 Grade 0, 0402; Manufacturer: Stackpole Electronics Inc; CompType: Resistor; Value: 100k; Res_ohm: 100000; Tolerance_%: 1; Power_W: 0.063; Value2: 0.063W; VDC_V: 50; TempCo: 100 ppm/C; SizeArea_mm2: 0.5; SizeZ_mm: 0.6; EIA_Code: E96; U/M: EA; AEC Category: Q200; AEC Qualified: Y; AEC Grade: 0
R68 R69 = CRCW04021K00JNED: RES, 1.0 k, 5%, 0.063 W, 0402; Manufacturer: Vishay-Dale; CompType: Resistor; Value: 1.0k; Res_ohm: 1000; Value_Code: 1k00; Tolerance_%: 5; Power_W: 0.063; Value2: 0.063W; VDC_V: 50; TempCo: 200 ppm/C; SizeArea_mm2: 0.5; SizeX_mm: 1; SizeZ_mm: 0.6; EIA_Code: E24; U/M: EA; AEC Category: Q200
R70 = CRCW04020000Z0ED: as R3 on sheet LP_Front_End_PWR
U15 = LMK00804BPW: Low Skew, 1-to-4 Multiplexed Differential/LVCMOS-to-LVCMOS/TTL Fanout Buffer, PW0016A; Manufacturer: Texas Instruments; SymbolCreator: a0411947; CompType: IC; U/M: EA
U16 U17 = SN74AUP1G80DCKR: LOW-POWER SINGLE POSITIVE-EDGE-TRIGGERED D-TYPE FLIP-FLOP, DCK0005A; Alternate PartNumber: SN74AUP1G80DCKT; Manufacturer: Texas Instruments; SymbolCreator: Altium; CompType: IC; U/M: EA
Y1 = ASEMB-16.000MHZ-XY-T: Oscillators, 16MHz, CMOS, 1.8 to 3.3V, SMD; Manufacturer: Abracon Corporation; Alternate PartNumber: ASEMB-16.000MHZ-LY-T; SymbolCreator: Altium; U/M: EA; TaMin_C: -40; TaMax_C: 105; Frequency Stability: ±10ppm

## Sheet LP_Front_End_AFE.SchDoc: AFE
size 431 x 279 mm; Date: Not shown in title block; ApprovedBy: Not shown in title block; CheckedBy: Not shown in title block; Author: Not shown in title block; CompanyName: Not shown in title block; DrawnBy: Jordan Radice; Engineer: Not shown in title block; Organization: Not shown in title block; Address1: Not shown in title block; Address2: Not shown in title block; Address3: Not shown in title block; Address4: Not shown in title block; DocumentNumber: 3; Revision: Use project parameter SCH_Rev; SheetNumber: 2; SheetTotal: 6; PageSetup: Record=PageOptions¦CenterHorizontal=True¦CenterVertical=True¦PrintScale=0.96¦XCorrection=1.00¦YCorrection=1.00¦PrintKind=0¦BorderSize=5000000¦LeftOffset=0¦BottomOffset=0¦Orientation=2¦PaperLength=1000¦PaperWidth=1000¦Scale=100¦PaperSource=15¦PrintQuality=-3¦MediaType=1¦DitherType=10¦PrintScaleMode=1¦PaperKind=11x17¦PaperIndex=17
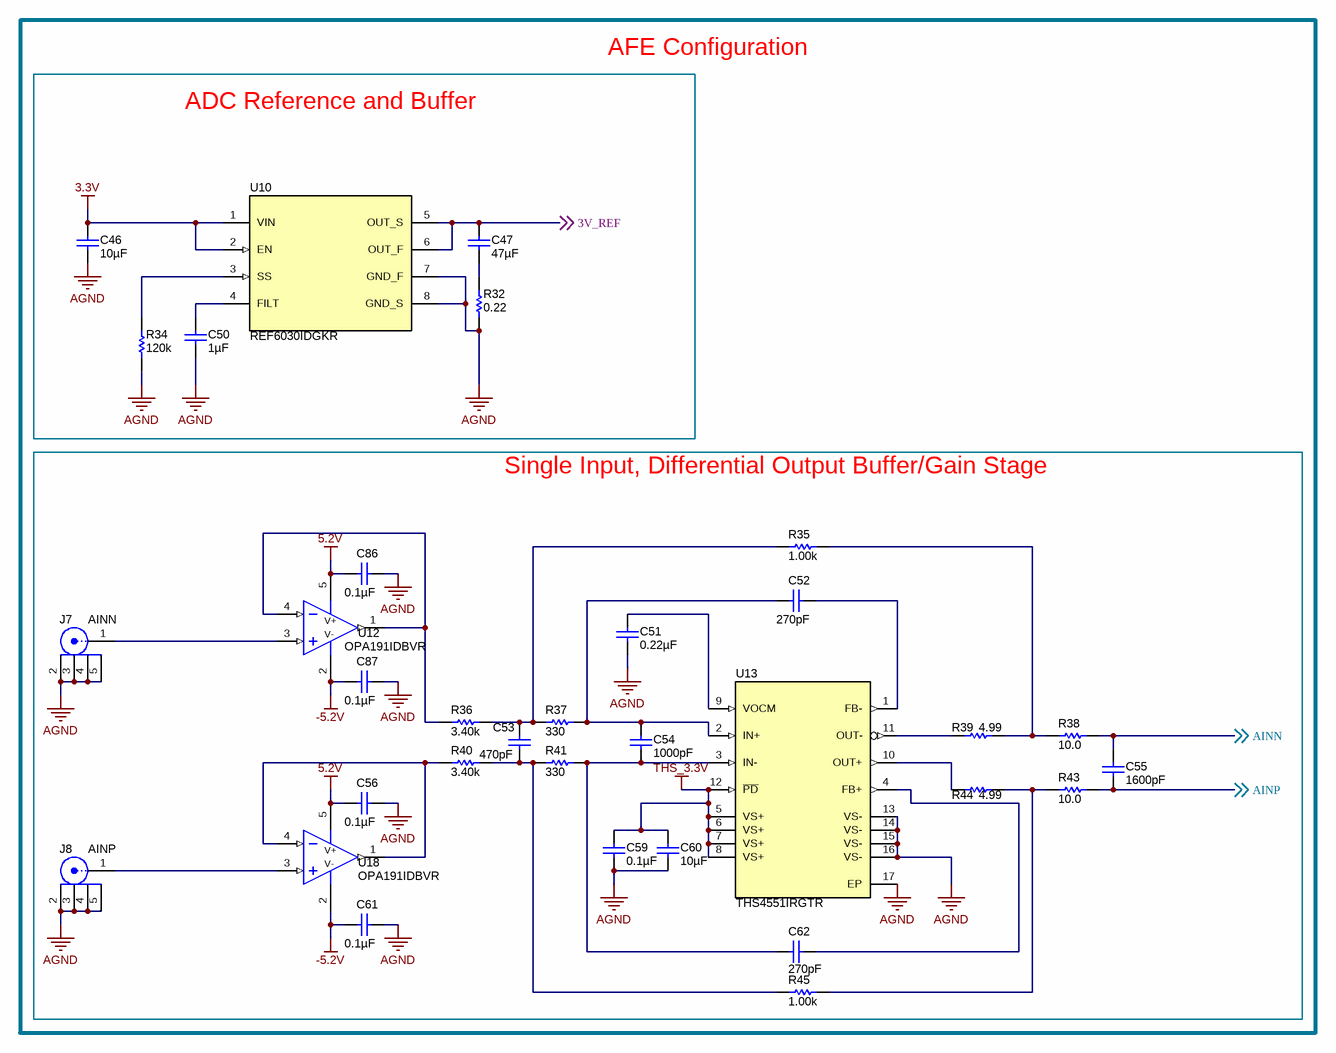
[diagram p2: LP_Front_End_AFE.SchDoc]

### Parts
C46  ValueDisplayed: 10µF  [0402]  (hidden comment: CL05A106MP5NUNC)
C47  ValueDisplayed: 47µF  [0805_HV]  (hidden comment: GRM21BR61A476ME15)
C50  ValueDisplayed: 1µF  [0402]  (hidden comment: GRM155R61A105KE15D)
C51  ValueDisplayed: 0.22µF  [0402]  (hidden comment: C1005X5R1A224K050BC)
C52  ValueDisplayed: 270pF  [0603]  (hidden comment: GRM1885C2A271JA01D)
C53  ValueDisplayed: 470pF  [0603]  (hidden comment: C1608C0G2A471J)
C54  ValueDisplayed: 1000pF  [0603]  (hidden comment: C1608C0G2A102J080AA)
C55  ValueDisplayed: 1600pF  [0805_HV]  (hidden comment: GRM2165C2A162JA01D)
C56  ValueDisplayed: 0.1µF  [0402]  (hidden comment: C1005X5R1A104K050BA)
C59  ValueDisplayed: 0.1µF  [0402]  (hidden comment: C1005X5R1A104K050BA)
C60  ValueDisplayed: 10µF  [0402]  (hidden comment: CL05A106MP5NUNC)
C61  ValueDisplayed: 0.1µF  [0402]  (hidden comment: C1005X5R1A104K050BA)
C62  ValueDisplayed: 270pF  [0603]  (hidden comment: GRM1885C2A271JA01D)
C86  ValueDisplayed: 0.1µF  [0402]  (hidden comment: C1005X5R1A104K050BA)
C87  ValueDisplayed: 0.1µF  [0402]  (hidden comment: C1005X5R1A104K050BA)
J7  AINN  [Amphenol_901-144-8RFX]
J8  AINP  [Amphenol_901-144-8RFX]
R32  ValueDisplayed: 0.22  [0402]  (hidden comment: ERJ-2BQFR22X)
R34  ValueDisplayed: 120k  [0402]  (hidden comment: CRCW0402120KFKED)
R35  ValueDisplayed: 1.00k  [0402]  (hidden comment: ERA-2AEB102X)
R36  ValueDisplayed: 3.40k  [0402]  (hidden comment: CRCW04023K40FKED)
R37  ValueDisplayed: 330  [0402]  (hidden comment: ERJ-2RKF3300X)
R38  ValueDisplayed: 10.0  [CPF0402]  (hidden comment: CPF0402B10RE1)
R39  ValueDisplayed: 4.99  [0402]  (hidden comment: CRCW04024R99FKED)
R40  ValueDisplayed: 3.40k  [0402]  (hidden comment: CRCW04023K40FKED)
R41  ValueDisplayed: 330  [0402]  (hidden comment: ERJ-2RKF3300X)
R43  ValueDisplayed: 10.0  [CPF0402]  (hidden comment: CPF0402B10RE1)
R44  ValueDisplayed: 4.99  [0402]  (hidden comment: CRCW04024R99FKED)
R45  ValueDisplayed: 1.00k  [0402]  (hidden comment: ERA-2AEB102X)
U10  REF6030IDGKR  [DGK0008A_N]
U12  OPA191IDBVR  [DBV0005A_N]
U13  THS4551IRGTR  [RGT0016C]
U18  OPA191IDBVR  [DBV0005A_N]

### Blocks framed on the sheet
ADC Reference and Buffer: C46 C47 C50 R32 R34 U10
Single Input, Differential Output Buffer/Gain Stage: C51-C56 C59-C62 C86 C87 J7 J8 R35-R41 R43-R45 U12 U13 U18

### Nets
3.3V: C46.1 U10.1(VIN) U10.2(EN)
5.2V: C56.2 C86.2 U12.5(V+) U18.5(V+)
-5.2V: C61.2 C87.2 U12.2(V-) U18.2(V-)
AGND: C46.2 C50.2 C51.2 C56.1 C59.2 C60.1 C61.1 C86.1 C87.1 J7.2 J7.3 J7.4 J7.5 J8.2 J8.3 J8.4 J8.5 R32.1 R34.1 U10.7(GND_F) U10.8(GND_S) U13.13(VS-) U13.14(VS-) U13.15(VS-) U13.16(VS-) U13.17(EP)
THS_3.3V: C59.1 C60.2 U13.5(VS+) U13.6(VS+) U13.7(VS+) U13.8(VS+) U13.12(~{PD})
3V_REF: C47.1 U10.5(OUT_S) U10.6(OUT_F) ; off-sheet 3V_REF
AINN: C55.1 R38.2 ; off-sheet AINN
AINP: C55.2 R43.2 ; off-sheet AINP
NetC47_2: C47.2 R32.2
NetC50_1: C50.1 U10.4(FILT)
NetC51_1: C51.1 U13.9(VOCM)
NetC52_1: C52.1 U13.1(FB-)
NetC52_2: C52.2 C54.1 R37.2 U13.2(IN+)
NetC53_1: C53.1 R35.1 R36.2 R37.1
NetC53_2: C53.2 R40.2 R41.1 R45.1
NetC54_2: C54.2 C62.2 R41.2 U13.3(IN-)
NetC62_1: C62.1 U13.4(FB+)
NetJ7_1: J7.1 U12.3(IN+)
NetJ8_1: J8.1 U18.3(IN+)
NetR34_2: R34.2 U10.3(SS)
NetR35_2: R35.2 R38.1 R39.2
NetR36_1: R36.1 U12.1(OUT) U12.4(IN-)
NetR39_1: R39.1 U13.11(OUT-)
NetR40_1: R40.1 U18.1(OUT) U18.4(IN-)
NetR43_1: R43.1 R44.2 R45.2
NetR44_1: R44.1 U13.10(OUT+)

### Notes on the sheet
- AFE Configuration

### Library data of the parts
C46 C60 = CL05A106MP5NUNC: as C77 on sheet LP_Front_End_ClockTree
C47 = GRM21BR61A476ME15: CAP, CERM, 47 µF, 10 V, +/- 20%, X5R, 0805; Manufacturer: MuRata; Polarized: N; CompType: Capacitor; Value: 47uF; U/M: EA; Cap_F: 0.000047; Tolerance_%: 20; Value1: Unknown; VDC_V: 10; Value2: 10V; TaMin_C: -55; TaMax_C: 85; Cap_Case: 0805; SizeArea_mm2: 2.5; SizeAreaWB_mm2: 6.75; SizeX_mm: 2; SizeY_mm: 1.25; SizeZ_mm: 1.45; AEC Category: Q200
C50 = GRM155R61A105KE15D: as C80 on sheet LP_Front_End_ClockTree
C51 = C1005X5R1A224K050BC: CAP, CERM, 0.22 µF, 10 V, +/- 10%, X5R, 0402; Manufacturer: TDK; Polarized: N; CompType: Capacitor; Value: 0.22uF; U/M: EA; Cap_F: 0.00000022; Tolerance_%: 10; Value1: Unknown; Value2: 10V; TaMin_C: -55; TaMax_C: 85; SizeArea_mm2: 0.5; SizeAreaWB_mm2: 3; SizeX_mm: 1; SizeZ_mm: 0.6; AEC Category: Q200
C52 C62 = GRM1885C2A271JA01D: CAP, CERM, 270 pF, 100 V, +/- 5%, C0G/NP0, 0603; Manufacturer: MuRata; Polarized: N; CompType: Capacitor; Value: 270pF; U/M: EA; Cap_F: 0.00000000027; Tolerance_%: 5; Value1: Unknown; VDC_V: 100; Value2: 100V; TaMin_C: -55; TaMax_C: 125; SizeArea_mm2: 1.28; SizeAreaWB_mm2: 4.68; SizeX_mm: 1.6; SizeY_mm: 0.8; SizeZ_mm: 1; AEC Category: Q200
C53 = C1608C0G2A471J: CAP, CERM, 470 pF, 100 V, +/- 5%, C0G/NP0, 0603; Manufacturer: TDK; Polarized: N; CompType: Capacitor; Value: 470pF; U/M: EA; Cap_F: 0.00000000047; Tolerance_%: 5; ESR_ohm: 0.0714; Value1: 0.0714 ohm; VDC_V: 100; Value2: 100V; TaMin_C: -55; TaMax_C: 125; SizeArea_mm2: 1.28; SizeAreaWB_mm2: 4.68; SizeX_mm: 1.6; SizeY_mm: 0.8; SizeZ_mm: 1; AEC Category: Q200
C54 = C1608C0G2A102J080AA: CAP, CERM, 1000 pF, 100 V, +/- 5%, C0G/NP0, 0603; Manufacturer: TDK; Polarized: N; CompType: Capacitor; Value: 1000pF; U/M: EA; Cap_F: 0.000000001; Tolerance_%: 5; ESR_ohm: 0.0589; Value1: 0.0589 ohm; VDC_V: 100; Value2: 100V; TaMin_C: -55; TaMax_C: 125; SizeArea_mm2: 1.28; SizeAreaWB_mm2: 4.68; SizeX_mm: 1.6; SizeY_mm: 0.8; SizeZ_mm: 1; AEC Category: Q200
C55 = GRM2165C2A162JA01D: CAP, CERM, 1600 pF, 100 V, +/- 5%, C0G/NP0, 0805; Manufacturer: MuRata; Polarized: N; CompType: Capacitor; Value: 1600pF; U/M: EA; Cap_F: 0.0000000016; Tolerance_%: 5; Value1: Unknown; VDC_V: 100; Value2: 100V; TaMin_C: -55; TaMax_C: 125; Cap_Case: 0805; SizeArea_mm2: 2.5; SizeAreaWB_mm2: 6.75; SizeX_mm: 2; SizeY_mm: 1.25; SizeZ_mm: 1.45; AEC Category: Q200
C56 C59 C61 C86 C87 = C1005X5R1A104K050BA: as C78 on sheet LP_Front_End_ClockTree
J7 J8 = 901-144-8RFX: SMA Straight Jack, Gold, 50 Ohm, TH; Manufacturer: Amphenol RF; SymbolCreator: X0208326
R32 = ERJ-2BQFR22X: RES, 0.22, 1%, 0.125 W, 0402; Manufacturer: Panasonic; CompType: Resistor; Value: 0.22; Value_Code: R220; Tolerance_%: 1; Power_W: 0.125; Value2: 0.125W; TempCo: 250 ppm/C; SizeArea_mm2: 0.5; SizeZ_mm: 0.6; EIA_Code: E96; U/M: EA; AEC Category: Q200
R34 = CRCW0402120KFKED: RES, 120 k, 1%, 0.063 W, 0402; Manufacturer: Vishay-Dale; CompType: Resistor; Value: 120k; Res_ohm: 120000; Tolerance_%: 1; Power_W: 0.063; Value2: 0.063W; VDC_V: 50; TempCo: 100 ppm/C; SizeArea_mm2: 0.5; SizeZ_mm: 0.6; U/M: EA; AEC Category: Q200
R35 R45 = ERA-2AEB102X: RES, 1.00 k, 0.1%, 0.063 W, 0402; Manufacturer: Panasonic; CompType: Resistor; Value: 1.00k; Res_ohm: 1000; Value_Code: 1k00; Tolerance_%: 0.1; Power_W: 0.063; Value2: 0.063W; VDC_V: 50; TempCo: 25 ppm/C; SizeArea_mm2: 0.5; SizeX_mm: 1; SizeZ_mm: 0.6; EIA_Code: E192; U/M: EA; AEC Category: Q200
R36 R40 = CRCW04023K40FKED: RES, 3.40 k, 1%, 0.063 W, 0402; Manufacturer: Vishay-Dale; CompType: Resistor; Value: 3.40k; Res_ohm: 3400; Value_Code: 3k40; Tolerance_%: 1; Power_W: 0.063; Value2: 0.063W; VDC_V: 50; TempCo: 100 ppm/C; SizeArea_mm2: 0.5; SizeZ_mm: 0.6; EIA_Code: E96; U/M: EA; AEC Category: Q200
R37 R41 = ERJ-2RKF3300X: RES, 330, 1%, 0.1 W, AEC-Q200 Grade 0, 0402; Manufacturer: Panasonic; CompType: Resistor; Value: 330; Value_Code: 330R; Tolerance_%: 1; Power_W: 0.1; Value2: 0.1W; VDC_V: 50; TempCo: 100 ppm/C; SizeArea_mm2: 0.5; SizeZ_mm: 0.6; U/M: EA; AEC Category: Q200; AEC Qualified: Y; AEC Grade: 0
R38 R43 = CPF0402B10RE1: RES, 10.0, 0.1%, 0.063 W, 0402; Manufacturer: TE Connectivity; CompType: Resistor; Value: 10.0; Res_ohm: 10; Value_Code: 10R0; Tolerance_%: 0.1; Power_W: 0.063; Value2: 0.063W; TempCo: 25 ppm/C; SizeArea_mm2: 0.5; SizeX_mm: 1; SizeZ_mm: 0.35; EIA_Code: E192; U/M: EA; AEC Category: Q200; AEC Qualified: N
R39 R44 = CRCW04024R99FKED: RES, 4.99, 1%, 0.063 W, 0402; Manufacturer: Vishay-Dale; CompType: Resistor; Value: 4.99; Value_Code: 4R99; Tolerance_%: 1; Power_W: 0.063; Value2: 0.063W; VDC_V: 50; TempCo: 100 ppm/C; SizeArea_mm2: 0.5; SizeZ_mm: 0.6; EIA_Code: E96; U/M: EA; AEC Category: Q200
U10 = REF6030IDGKR: High-Precision Voltage Reference with Integrated High-Bandwidth Buffer, DGK0008A (VSSOP-8); Alternate PartNumber: REF6030IDGKT; Manufacturer: Texas Instruments; SymbolCreator: Altium; SizeArea_mm2: 15.655; SizeAreaWB_mm2: 35.955; SizeX_mm: 5.05; SizeY_mm: 3.1; SizeZ_mm: 1.1; CompType: IC; U/M: EA
U12 U18 = OPA191IDBVR: 36-V, Low Power, Precision, CMOS, Rail-to-Rail Input/Output, Low Offset Voltage, Low Input Bias Current Op Amp, DBV0005A (SOT-5); Alternate PartNumber: OPA191IDBVT; Manufacturer: Texas Instruments; SizeArea_mm2: 8.12; SizeAreaWB_mm2: 14.82; SizeX_mm: 2.8; SizeY_mm: 2.9; SizeZ_mm: 1.45; CompType: IC; U/M: EA
U13 = THS4551IRGTR: Low Noise, Precision, 150MHz, Fully Differential Amplifier, RGT0016C (VQFN-16); Alternate PartNumber: THS4551IRGTT; Manufacturer: Texas Instruments; SymbolCreator: Altium; SizeArea_mm2: 16; SizeAreaWB_mm2: 25; SizeX_mm: 4; SizeZ_mm: 1; CompType: IC; U/M: EA

## Sheet LP_Front_End_ADC.SchDoc: ADC
size 431 x 279 mm; Date: Not shown in title block; ApprovedBy: Not shown in title block; CheckedBy: Not shown in title block; Author: Not shown in title block; CompanyName: Not shown in title block; DrawnBy: Jordan Radice; Engineer: Not shown in title block; Organization: Not shown in title block; Address1: Not shown in title block; Address2: Not shown in title block; Address3: Not shown in title block; Address4: Not shown in title block; DocumentNumber: 3; Revision: Use project parameter SCH_Rev; SheetNumber: 3; SheetTotal: 6; PageSetup: Record=PageOptions¦CenterHorizontal=True¦CenterVertical=True¦PrintScale=0.96¦XCorrection=1.00¦YCorrection=1.00¦PrintKind=0¦BorderSize=5000000¦LeftOffset=0¦BottomOffset=0¦Orientation=2¦PaperLength=1000¦PaperWidth=1000¦Scale=100¦PaperSource=15¦PrintQuality=-3¦MediaType=1¦DitherType=10¦PrintScaleMode=1¦PaperKind=11x17¦PaperIndex=17
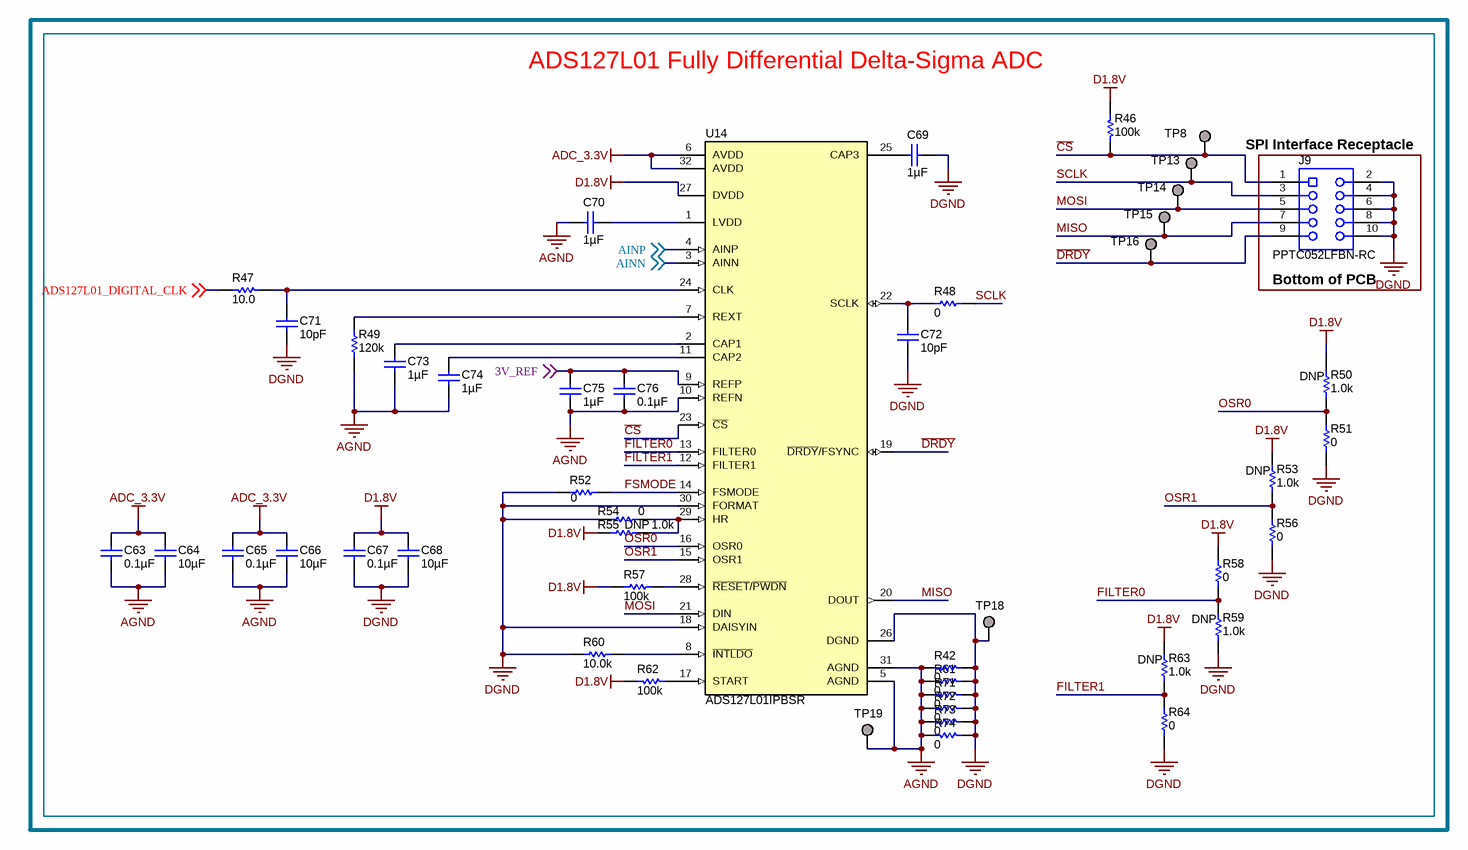
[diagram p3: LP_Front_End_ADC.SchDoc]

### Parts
C63  ValueDisplayed: 0.1µF  [0402]  (hidden comment: C1005X5R1A104K050BA)
C64  ValueDisplayed: 10µF  [0402]  (hidden comment: CL05A106MP5NUNC)
C65  ValueDisplayed: 0.1µF  [0402]  (hidden comment: C1005X5R1A104K050BA)
C66  ValueDisplayed: 10µF  [0402]  (hidden comment: CL05A106MP5NUNC)
C67  ValueDisplayed: 0.1µF  [0402]  (hidden comment: C1005X5R1A104K050BA)
C68  ValueDisplayed: 10µF  [0402]  (hidden comment: CL05A106MP5NUNC)
C69  ValueDisplayed: 1µF  [0402]  (hidden comment: GRM155R61A105KE15D)
C70  ValueDisplayed: 1µF  [0402]  (hidden comment: GRM155R61A105KE15D)
C71  ValueDisplayed: 10pF  [0603]  (hidden comment: 06035A100JAT2A)
C72  ValueDisplayed: 10pF  [0603]  (hidden comment: GRM1885C2A100JA01D)
C73  ValueDisplayed: 1µF  [0402]  (hidden comment: GRM155R61A105KE15D)
C74  ValueDisplayed: 1µF  [0402]  (hidden comment: GRM155R61A105KE15D)
C75  ValueDisplayed: 1µF  [0402]  (hidden comment: GRM155R61A105KE15D)
C76  ValueDisplayed: 0.1µF  [0402]  (hidden comment: C1005X5R1A104K050BA)
J9  PPTC052LFBN-RC  [Sullins_xPxC052LFBN]
R42  ValueDisplayed: 0  [0402]  (hidden comment: DNP)
R46  ValueDisplayed: 100k  [0402]  (hidden comment: RMCF0402FT100K)
R47  ValueDisplayed: 10.0  [0402]  (hidden comment: CRCW040210R0FKED)
R48  ValueDisplayed: 0  [0402]  (hidden comment: CRCW04020000Z0ED)
R49  ValueDisplayed: 120k  [0402]  (hidden comment: CRCW0402120KFKED)
R50  DNP  ValueDisplayed: 1.0k  [0402]
R51  ValueDisplayed: 0  [0402]  (hidden comment: CRCW04020000Z0ED)
R52  ValueDisplayed: 0  [0402]  (hidden comment: CRCW04020000Z0ED)
R53  DNP  ValueDisplayed: 1.0k  [0402]
R54  ValueDisplayed: 0  [0402]  (hidden comment: CRCW04020000Z0ED)
R55  DNP  ValueDisplayed: 1.0k  [0402]
R56  ValueDisplayed: 0  [0402]  (hidden comment: CRCW04020000Z0ED)
R57  ValueDisplayed: 100k  [0402]  (hidden comment: CRCW0402100KFKED)
R58  ValueDisplayed: 0  [0402]  (hidden comment: CRCW04020000Z0ED)
R59  DNP  ValueDisplayed: 1.0k  [0402]
R60  ValueDisplayed: 10.0k  [0402]  (hidden comment: RK73H1ETTP1002F)
R61  ValueDisplayed: 0  [0402]  (hidden comment: DNP)
R62  ValueDisplayed: 100k  [0402]  (hidden comment: RMCF0402FT100K)
R63  DNP  ValueDisplayed: 1.0k  [0402]
R64  ValueDisplayed: 0  [0402]  (hidden comment: CRCW04020000Z0ED)
R71  ValueDisplayed: 0  [0402]  (hidden comment: DNP)
R72  ValueDisplayed: 0  [0402]  (hidden comment: DNP)
R73  ValueDisplayed: 0  [0402]  (hidden comment: DNP)
R74  ValueDisplayed: 0  [0402]  (hidden comment: DNP)
TP8  TESTPOINT  [Harwin_S2751-46R]  (value not drawn)  (no BOM)
TP13  TESTPOINT  [Harwin_S2751-46R]  (value not drawn)  (no BOM)
TP14  TESTPOINT  [Harwin_S2751-46R]  (value not drawn)  (no BOM)
TP15  TESTPOINT  [Harwin_S2751-46R]  (value not drawn)  (no BOM)
TP16  TESTPOINT  [Harwin_S2751-46R]  (value not drawn)  (no BOM)
TP18  TESTPOINT  [Harwin_S2751-46R]  (value not drawn)  (no BOM)
TP19  TESTPOINT  [Harwin_S2751-46R]  (value not drawn)  (no BOM)
U14  ADS127L01IPBSR  [PBS0032A_N]

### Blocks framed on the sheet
ADS127L01 Fully Differential Delta-Sigma ADC: C63-C76 J9 R42 R46-R64 R71-R74 TP8 TP13-TP16 TP18 TP19 U14

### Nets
ADC_3.3V: C63.2 C64.1 C65.2 C66.1 U14.6(AVDD) U14.32(AVDD)
AGND: C63.1 C64.2 C65.1 C66.2 C70.1 C73.2 C74.2 C75.2 C76.1 R42.2 R49.1 R61.2 R71.2 R72.2 R73.2 R74.2 TP19.1 U14.5(AGND) U14.10(REFN) U14.31(AGND)
D1.8V: C67.2 C68.1 R46.1 R50.2 R53.2 R55.2 R57.2 R58.2 R62.2 R63.2 U14.27(DVDD)
DGND: C67.1 C68.2 C69.2 C71.2 C72.2 J9.2 J9.4 J9.6 J9.8 J9.10 R42.1 R51.1 R52.2 R54.1 R56.1 R59.1 R60.2 R61.1 R64.1 R71.1 R72.1 R73.1 R74.1 TP18.1 U14.18(DAISYIN) U14.26(DGND) U14.30(FORMAT)
3V_REF: C75.1 C76.2 U14.9(REFP) ; off-sheet 3V_REF
~{CS}: J9.1 R46.2 TP8.1 U14.23(~{CS})
~{DRDY}: J9.9 TP16.1 U14.19(~{DRDY}/FSYNC)
ADS127L01_DIGITAL_CLK: R47.2 ; off-sheet ADS127L01_DIGITAL_CLK
AINN: U14.3(AINN) ; off-sheet AINN
AINP: U14.4(AINP) ; off-sheet AINP
FILTER0: R58.1 R59.2 U14.13(FILTER0)
FILTER1: R63.1 R64.2 U14.12(FILTER1)
FSMODE: R52.1 U14.14(FSMODE)
MISO: J9.7 TP15.1 U14.20(DOUT)
MOSI: J9.5 TP14.1 U14.21(DIN)
OSR0: R50.1 R51.2 U14.16(OSR0)
OSR1: R53.1 R56.2 U14.15(OSR1)
SCLK: J9.3 R48.2 TP13.1
NetC69_1: C69.1 U14.25(CAP3)
NetC70_2: C70.2 U14.1(LVDD)
NetC71_1: C71.1 R47.1 U14.24(CLK)
NetC72_1: C72.1 R48.1 U14.22(SCLK)
NetC73_1: C73.1 U14.2(CAP1)
NetC74_1: C74.1 U14.11(CAP2)
NetR49_2: R49.2 U14.7(REXT)
NetR54_2: R54.2 R55.1 U14.29(HR)
NetR57_1: R57.1 U14.28(~{RESET}/~{PWDN})
NetR60_1: R60.1 U14.8(~{INTLDO})
NetR62_1: R62.1 U14.17(START)

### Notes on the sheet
- SPI Interface Receptacle
- (near J9) Bottom of PCB

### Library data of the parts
C63 C65 C67 C76 = C1005X5R1A104K050BA: as C78 on sheet LP_Front_End_ClockTree
C64 C66 C68 = CL05A106MP5NUNC: as C77 on sheet LP_Front_End_ClockTree
C69 C70 C73-C75 = GRM155R61A105KE15D: as C80 on sheet LP_Front_End_ClockTree
C71 = 06035A100JAT2A: CAP, CERM, 10 pF, 50 V, +/- 5%, C0G/NP0, 0603; Manufacturer: AVX; Polarized: N; CompType: Capacitor; Value: 10pF; U/M: EA; Cap_F: 0.00000000001; Tolerance_%: 5; ESR_ohm: 0.403; Value1: 0.403 ohm; VDC_V: 50; Value2: 50V; TaMin_C: -55; TaMax_C: 125; SizeArea_mm2: 1.28; SizeAreaWB_mm2: 4.68; SizeX_mm: 1.6; SizeY_mm: 0.8; SizeZ_mm: 1; AEC Category: Q200
C72 = GRM1885C2A100JA01D: CAP, CERM, 10 pF, 100 V, +/- 5%, C0G/NP0, 0603; Manufacturer: MuRata; Polarized: N; CompType: Capacitor; Value: 10pF; U/M: EA; Cap_F: 0.00000000001; Tolerance_%: 5; Value1: Unknown; VDC_V: 100; Value2: 100V; TaMin_C: -55; TaMax_C: 125; AEC Category: Q200; SizeArea_mm2: 1.28; SizeAreaWB_mm2: 4.68; SizeX_mm: 1.6; SizeY_mm: 0.8; SizeZ_mm: 1
J9 = PPTC052LFBN-RC: Receptacle, 2.54mm, 5x2, Gold, TH; Manufacturer: Sullins Connector Solutions; SymbolCreator: a0412235; Pitch_mm: 2.54; Gender: Female; Row_Count: 2
R42 R48 R51 R52 R54 R56 R58 R61 R64 R71-R74 = CRCW04020000Z0ED: as R3 on sheet LP_Front_End_PWR
R46 R62 = RMCF0402FT100K: as R67 on sheet LP_Front_End_ClockTree
R47 = CRCW040210R0FKED: RES, 10.0, 1%, 0.063 W, 0402; Manufacturer: Vishay-Dale; CompType: Resistor; Value: 10.0; Res_ohm: 10; Value_Code: 10R0; Tolerance_%: 1; Power_W: 0.063; Value2: 0.063W; VDC_V: 50; TempCo: 100 ppm/C; SizeArea_mm2: 0.5; SizeZ_mm: 0.6; EIA_Code: E96; U/M: EA; AEC Category: Q200
R49 = CRCW0402120KFKED: as R34 on sheet LP_Front_End_AFE
R50 R53 R55 R59 R63 = CRCW04021K00JNED: as R68 on sheet LP_Front_End_ClockTree
R57 = CRCW0402100KFKED: as R2 on sheet LP_Front_End_PWR
R60 = RK73H1ETTP1002F: RES, 10.0 k, 1%, 0.063 W, AEC-Q200 Grade 0, 0402; Manufacturer: KOA Speer; CompType: Resistor; Value: 10.0k; Res_ohm: 10000; Value_Code: 10k0; Tolerance_%: 1; Power_W: 0.063; Value2: 0.063W; VDC_V: 50; TempCo: 100 ppm/C; SizeArea_mm2: 0.5; SizeZ_mm: 0.6; EIA_Code: E96; U/M: EA; AEC Category: Q200; AEC Qualified: Y; AEC Grade: 0
TP8 TP13-TP16 TP18 TP19 = S2751-46R: Test Point, SMT; Manufacturer: Harwin
U14 = ADS127L01IPBSR: 24-Bit, 512kSPS, Delta-Sigma ADC, PBS0032A (TQFP-32); Manufacturer: Texas Instruments; SymbolCreator: x0208326; SizeArea_mm2: 49; SizeAreaWB_mm2: 81; SizeX_mm: 7; SizeZ_mm: 1.2; CompType: IC; U/M: EA

## Sheet LP_Front_End_Block_Diagram.SchDoc: Block Diagram
size 431 x 279 mm; Date: Not shown in title block; ApprovedBy: Not shown in title block; CheckedBy: Not shown in title block; Author: Not shown in title block; CompanyName: Not shown in title block; Engineer: Not shown in title block; Organization: Not shown in title block; Address1: Not shown in title block; Address2: Not shown in title block; Address3: Not shown in title block; Address4: Not shown in title block; DocumentNumber: 1; Revision: Use project parameter SCH_Rev; SheetNumber: 1; SheetTotal: 6; PageSetup: Record=PageOptions¦CenterHorizontal=True¦CenterVertical=True¦PrintScale=0.96¦XCorrection=1.00¦YCorrection=1.00¦PrintKind=0¦BorderSize=5000000¦LeftOffset=0¦BottomOffset=0¦Orientation=2¦PaperLength=1000¦PaperWidth=1000¦Scale=100¦PaperSource=15¦PrintQuality=-3¦MediaType=1¦DitherType=10¦PrintScaleMode=1¦PaperKind=Tabloid (11 x 17")¦PaperIndex=17
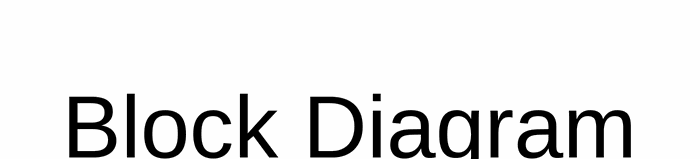
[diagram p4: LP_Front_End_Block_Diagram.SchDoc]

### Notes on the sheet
- Block Diagram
